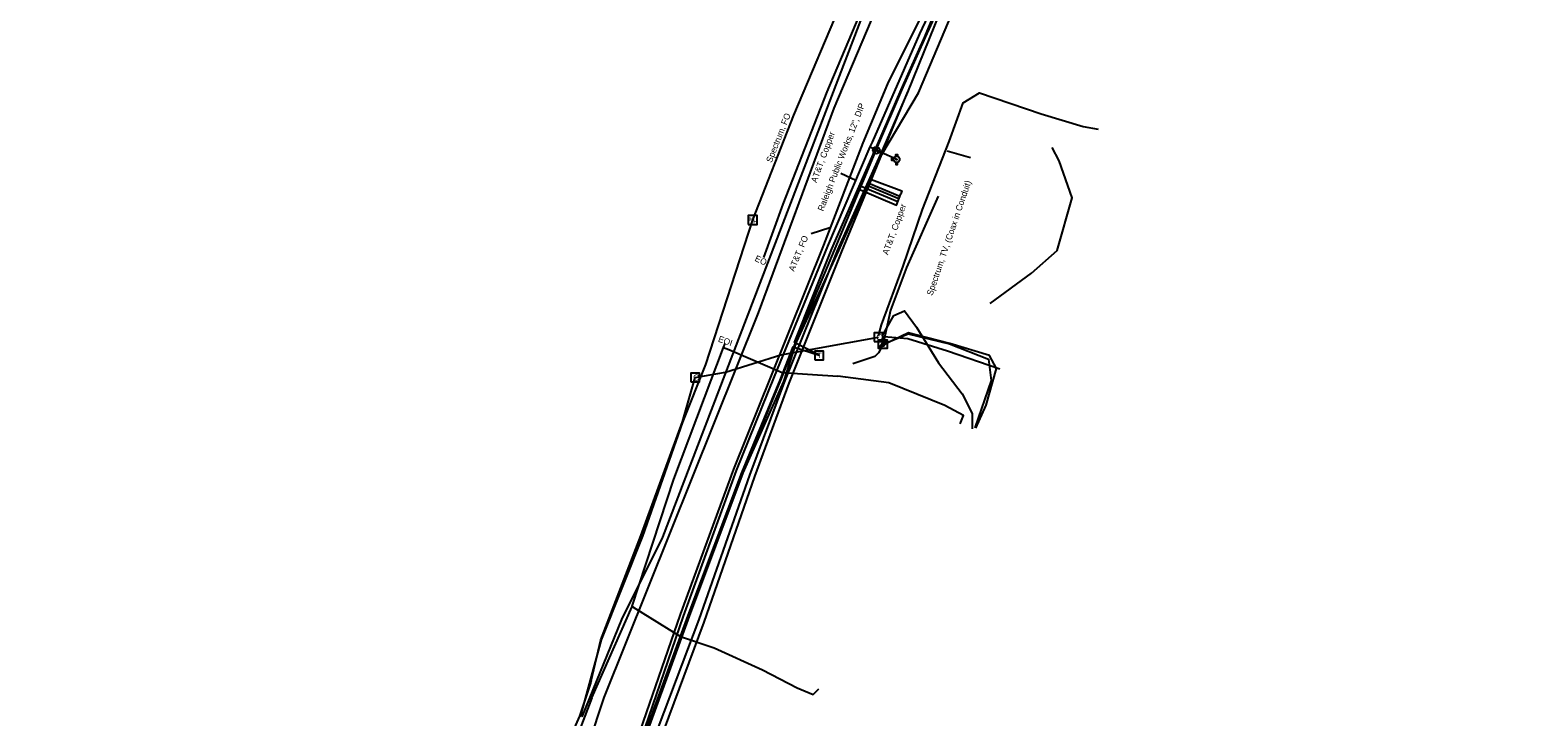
# Model space of a CAD drawing. Extents: x 2070721 to 2083340, y 729290 to 737883.
# Drawn here: x 2080953 to 2081917, y 733835 to 734274 of the extents above; entities that cross this region are included whole.
import ezdxf

# ---------------------------------------------------------------- set-up
doc = ezdxf.new("R2010")
doc.units = 0
for name, color, linetype in [('Exist Utilities Gas UG Line SUE LOS B', 7, 'Continuous'), ('Exist Utilities Gas Valve Text', 7, 'Continuous'), ('Exist Utilities Other Pole With Base Text', 7, 'Continuous'), ('Exist Utilities Other Unknown UG SUE LOS B', 7, 'Continuous'), ('Exist Utilities Power Transformer CELL', 7, 'Continuous'), ('Exist Utilities Power UG Cable SUE LOS B', 7, 'Continuous'), ('Exist Utilities Telephone Pedestal CELL', 7, 'Continuous'), ('Exist Utilities Telephone UG Cable SUE LOS C', 7, 'Continuous'), ('Exist Utilities Telephone UG Cable SUE LOS C Leader', 7, 'Continuous'), ('Exist Utilities Telephone UG Cable SUE LOS C Text', 7, 'Continuous'), ('Exist Utilities Telephone UG FO SUE LOS B', 7, 'Continuous'), ('Exist Utilities Telephone UG FO SUE LOS B Leader', 7, 'Continuous'), ('Exist Utilities Telephone UG FO SUE LOS B Text', 7, 'Continuous'), ('Exist Utilities TV Hand Hole CELL', 7, 'Continuous'), ('Exist Utilities TV Pedestal CELL', 7, 'Continuous'), ('Exist Utilities TV UG Cable SUE LOS B', 7, 'Continuous'), ('Exist Utilities TV UG Cable SUE LOS B Leader', 7, 'Continuous'), ('Exist Utilities TV UG Cable SUE LOS B Text', 7, 'Continuous'), ('Exist Utilities TV UG Cable SUE LOS C', 7, 'Continuous'), ('Exist Utilities TV UG FO Cable SUE LOS B', 7, 'Continuous'), ('Exist Utilities TV UG FO Cable SUE LOS B Text', 7, 'Continuous'), ('Exist Utilities Water Fire Hydrant CELL', 7, 'Continuous'), ('Exist Utilities Water UG Line SUE LOS B', 7, 'Continuous'), ('Exist Utilities Water UG Line SUE LOS B Leader', 7, 'Continuous'), ('Exist Utilities Water UG Line SUE LOS B Text', 7, 'Continuous'), ('Exist Utilities Water Valve CELL', 7, 'Continuous')]:
    doc.layers.add(name, color=color, linetype=linetype)

msp = doc.modelspace()

# ---------------------------------------------------------------- linework, layer by layer
at = {"layer": 'Exist Utilities Gas UG Line SUE LOS B'}
for points in [[(2081338.03, 733905.19), (2081338.21, 733905.54), (2081364.78, 733986.66), (2081384.36, 734038.69), (2081396.54, 734070.93), (2081397.51, 734073.37)], [(2081396.54, 734070.93), (2081399.83, 734069.53), (2081434.09, 734054.98), (2081469.65, 734052.56)], [(2081547.78, 734022.11), (2081549.89, 734027.5), (2081538.01, 734033.8), (2081502.22, 734048.37), (2081474.49, 734051.91), (2081469.65, 734052.56)], [(2081312.38, 733846.82), (2081338.03, 733905.19)], [(2081338.03, 733905.19), (2081340.5, 733903.66), (2081369.1, 733885.95), (2081390.43, 733878.76), (2081421.33, 733864.71), (2081443.53, 733853.28), (2081453.74, 733849.03), (2081457.45, 733852.48)], [(2081157.6, 733423.49), (2081157.75, 733423.93), (2081190.43, 733509.93), (2081219.7, 733588.19), (2081252.91, 733674.58), (2081286.02, 733770.88), (2081302.57, 733820.59), (2081312.47, 733846.89)]]:
    msp.add_lwpolyline(points, dxfattribs=at)
at = {"layer": 'Exist Utilities Other Unknown UG SUE LOS B'}
for points in [[(2081306.2, 733834.68), (2081331.52, 733896.97), (2081357.74, 733949.48), (2081551.49, 734455.55)], [(2081422.3, 734128.51), (2081434.71, 734162.6), (2081462.76, 734234.36), (2081499.05, 734320.38), (2081503.56, 734331.04)]]:
    msp.add_lwpolyline(points, dxfattribs=at)
at = {"layer": 'Exist Utilities Power Transformer CELL'}
msp.add_line((2081498.49, 734073.2), (2081498.49, 734073.2), dxfattribs=at)
msp.add_lwpolyline([(2081495.64, 734075.81), (2081501.2, 734075.81), (2081501.2, 734070.26), (2081495.64, 734070.26)], close=True, dxfattribs=at)
for points in [[(2081495.64, 734070.26), (2081498.29, 734074.2), (2081498.92, 734071.99), (2081501.2, 734075.81)], [(2081495.71, 734070.26), (2081498.29, 734073.99), (2081498.87, 734071.81), (2081501.2, 734075.66)]]:
    msp.add_lwpolyline(points, dxfattribs=at)
at = {"layer": 'Exist Utilities Power UG Cable SUE LOS B'}
for points in [[(2081566.99, 734098.99), (2081593.32, 734118.39), (2081609.81, 734133.03), (2081619.44, 734166.59), (2081611.13, 734190.33), (2081606.68, 734198.77)], [(2081533.76, 734167.78), (2081513.41, 734122.01), (2081503.32, 734094.68), (2081498.5, 734073.2)], [(2081498.49, 734073.2), (2081495.51, 734067.56), (2081493.34, 734065.2), (2081479.14, 734060.39)], [(2081557.74, 734019.38), (2081564.5, 734034.09), (2081571.11, 734057.42), (2081566.57, 734065.71), (2081541.21, 734073.53), (2081514.71, 734080.22), (2081499.18, 734072.89)], [(2081499.39, 734072.79), (2081502.13, 734074.42), (2081514.62, 734079.56), (2081541, 734073.24), (2081566.01, 734063.53), (2081567.68, 734049.7), (2081557.19, 734019.59)]]:
    msp.add_lwpolyline(points, dxfattribs=at)
at = {"layer": 'Exist Utilities Telephone Pedestal CELL'}
msp.add_line((2081457.55, 734065.88), (2081457.55, 734065.88), dxfattribs=at)
msp.add_lwpolyline([(2081454.82, 734063.06), (2081460.42, 734063.06), (2081460.42, 734068.65), (2081454.82, 734068.65), (2081454.82, 734063.06)], dxfattribs=at)
at = {"layer": 'Exist Utilities Telephone UG Cable SUE LOS C'}
for points in [[(2080953.21, 732796.69), (2081054.09, 733077.62), (2081111.09, 733245.57), (2081176.08, 733423.78), (2081231.97, 733580.28), (2081320.16, 733847.08), (2081418.84, 734093.09), (2081467.34, 734224.03), (2081494.06, 734287.2), (2081526.74, 734352.01), (2081556, 734404.62), (2081808.13, 734757.73), (2081845.73, 734804.26), (2081874.67, 734821.58), (2081898.66, 734810.94), (2081917.15, 734795.51)], [(2081296.4, 733658.15), (2081287.8, 733664.8), (2081303.6, 733706.37), (2081324.3, 733763.14), (2081337.34, 733798.98), (2081373.91, 733899.45), (2081408.19, 733990.78), (2081432.67, 734050.1), (2081441.11, 734071.31), (2081457.65, 734065.9), (2081441.97, 734074.17), (2081465.76, 734134.1), (2081494.56, 734199.64), (2081510.1, 734235.63), (2081525.23, 734269.67), (2081532.48, 734287.03), (2081544.5, 734311.63), (2081547.42, 734317.11)], [(2081296.31, 733658.4), (2081289.16, 733664.06), (2081304.03, 733706.05), (2081324.8, 733762.93), (2081337.87, 733799.07), (2081374.5, 733899.39), (2081408.89, 733991.2), (2081433.1, 734049.99), (2081442.72, 734074.23), (2081467.51, 734133.17), (2081494.99, 734199.31), (2081510.48, 734235.4), (2081525.69, 734269.34), (2081544.76, 734311.53), (2081547.99, 734317.07)], [(2081296.39, 733658.2), (2081307.45, 733685.25), (2081318.77, 733704.29), (2081345.73, 733792.08), (2081384.21, 733895.19), (2081416.52, 733988.47), (2081438.43, 734048.05), (2081472.15, 734132.3), (2081497.77, 734194.3), (2081521.27, 734233.79), (2081552.24, 734307.58), (2081554.35, 734311.73)], [(2081296.32, 733658.45), (2081292.23, 733667.87), (2081304.13, 733678.02), (2081310.51, 733703.91), (2081344.1, 733799.36), (2081380.98, 733896.99), (2081413.3, 733989.25), (2081435.43, 734048.8), (2081469.68, 734133.31), (2081498.8, 734198.46), (2081514.35, 734234.28), (2081535.34, 734285.71)], [(2081296.61, 733659.46), (2081294.36, 733663.37), (2081305.04, 733689.21), (2081304.27, 733706.32), (2081325.1, 733762.82), (2081338.41, 733798.86), (2081374.68, 733899.14), (2081409.12, 733990.75), (2081435.11, 734049.06), (2081443.22, 734074.28), (2081470.18, 734132.86), (2081499.3, 734198.06), (2081514.4, 734234.31)]]:
    msp.add_lwpolyline(points, dxfattribs=at)
at = {"layer": 'Exist Utilities Telephone UG Cable SUE LOS C Leader'}
for p, q in [((2081484.48, 734174.03), (2081507.94, 734164.17)), ((2081488.23, 734174.81), (2081508.68, 734166.13)), ((2081489.45, 734176.03), (2081509.23, 734167.66))]:
    msp.add_line(p, q, dxfattribs=at)
for points in [[(2081491.14, 734178.26), (2081510.46, 734171.14), (2081509.82, 734169.24)], [(2081482.62, 734172.39), (2081507.12, 734161.92), (2081509.82, 734169.24)]]:
    msp.add_lwpolyline(points, dxfattribs=at)
at = {"layer": 'Exist Utilities Telephone UG FO SUE LOS B'}
msp.add_lwpolyline([(2081248.81, 733567.64), (2081281.2, 733657.22), (2081333.49, 733797.21), (2081369.06, 733900.16), (2081403.11, 733993), (2081427.18, 734053.08), (2081460.75, 734136.42), (2081485.85, 734201.8), (2081501.51, 734239.63), (2081538.45, 734313.8), (2081542.88, 734322.62)], dxfattribs=at)
at = {"layer": 'Exist Utilities Telephone UG FO SUE LOS B Leader'}
msp.add_line((2081464.59, 734147.47), (2081452.54, 734143.52), dxfattribs=at)
at = {"layer": 'Exist Utilities TV Hand Hole CELL'}
msp.add_line((2081415.06, 734152.42), (2081415.06, 734152.42), dxfattribs=at)
msp.add_lwpolyline([(2081412.19, 734149.55), (2081417.94, 734149.55), (2081417.94, 734155.3), (2081412.19, 734155.3), (2081412.19, 734149.55)], dxfattribs=at)
at = {"layer": 'Exist Utilities TV Pedestal CELL'}
for p, q in [((2081495.55, 734077.52), (2081495.55, 734077.52)), ((2081378.38, 734051.63), (2081378.38, 734051.63))]:
    msp.add_line(p, q, dxfattribs=at)
for points in [[(2081492.78, 734074.75), (2081498.33, 734074.75), (2081498.33, 734080.3), (2081492.78, 734080.3), (2081492.78, 734074.75)], [(2081375.61, 734048.85), (2081381.16, 734048.85), (2081381.16, 734054.4), (2081375.61, 734054.4), (2081375.61, 734048.85)]]:
    msp.add_lwpolyline(points, dxfattribs=at)
at = {"layer": 'Exist Utilities TV UG Cable SUE LOS B'}
for points in [[(2081495.68, 734078.41), (2081497.44, 734085.32), (2081511.29, 734122.81), (2081523.68, 734159.18), (2081540.68, 734202.67), (2081549.71, 734227.45), (2081560.24, 734233.78), (2081599.68, 734220.27), (2081626.49, 734212.19), (2081636.02, 734210.48)], [(2081498.25, 734078.67), (2081505.35, 734091.29), (2081512.22, 734094.34), (2081519.8, 734083.82), (2081533.95, 734061.11), (2081549.19, 734041.27), (2081555.57, 734028.72), (2081555.57, 734018.83)], [(2081378.38, 734051.63), (2081388.01, 734053.44), (2081397.72, 734055.21), (2081433.17, 734066.11), (2081495.5, 734077.4)], [(2081573.07, 734056.98), (2081539.64, 734068.54), (2081514.32, 734076.46), (2081498.99, 734077.79)]]:
    msp.add_lwpolyline(points, dxfattribs=at)
at = {"layer": 'Exist Utilities TV UG Cable SUE LOS B Leader'}
msp.add_line((2081539.58, 734196.78), (2081554.51, 734192.46), dxfattribs=at)
at = {"layer": 'Exist Utilities TV UG Cable SUE LOS C'}
for points in [[(2081311.88, 733857.73), (2081318.02, 733883.97), (2081343.7, 733950.47), (2081370.25, 734023.44), (2081378.31, 734051.68)], [(2081311.88, 733857.73), (2081311.69, 733856.75), (2081304.36, 733835.18), (2081292.68, 733808.59), (2081285.24, 733806.52)]]:
    msp.add_lwpolyline(points, dxfattribs=at)
at = {"layer": 'Exist Utilities TV UG FO Cable SUE LOS B'}
msp.add_lwpolyline([(2081305.07, 733834.62), (2081318.51, 733883.96), (2081344.94, 733950.24), (2081370.6, 734023.22), (2081385.26, 734060), (2081415.18, 734152.65), (2081441.55, 734219.41), (2081473.57, 734295.5), (2081490.54, 734320.82), (2081495.24, 734327.83)], dxfattribs=at)
at = {"layer": 'Exist Utilities Water Fire Hydrant CELL'}
msp.add_line((2081507.14, 734191.19), (2081507.14, 734191.19), dxfattribs=at)
for points in [[(2081505.23, 734191.7), (2081503.94, 734191.7), (2081503.94, 734190.67), (2081505.23, 734190.67)], [(2081506.62, 734193.1), (2081506.62, 734194.39), (2081507.65, 734194.39), (2081507.65, 734193.07)], [(2081506.62, 734189.27), (2081506.62, 734187.99), (2081507.65, 734187.99), (2081507.65, 734189.3)]]:
    msp.add_lwpolyline(points, dxfattribs=at)
for radius in [1.98, 0.243]:
    msp.add_circle((2081507.14, 734191.19), radius, dxfattribs=at)
at = {"layer": 'Exist Utilities Water UG Line SUE LOS B'}
for points in [[(2081490.29, 734199.14), (2081491.68, 734202.17), (2081522.1, 734271.61), (2081541.68, 734313.21), (2081545.19, 734320.14)], [(2081335.25, 733795.02), (2081336.53, 733799.05), (2081370.86, 733898.95), (2081404.78, 733992.12), (2081429.05, 734052.38), (2081463.19, 734135.61), (2081490.29, 734199.14)], [(2081490.29, 734199.14), (2081496.9, 734195.96), (2081507.42, 734191.29)]]:
    msp.add_lwpolyline(points, dxfattribs=at)
at = {"layer": 'Exist Utilities Water UG Line SUE LOS B Leader'}
msp.add_line((2081481.14, 734177.71), (2081471.52, 734182.16), dxfattribs=at)
at = {"layer": 'Exist Utilities Water Valve CELL'}
msp.add_lwpolyline([(2081495.74, 734198.64), (2081492.59, 734195.49), (2081494.16, 734197.07), (2081495.74, 734195.49), (2081492.59, 734198.64)], dxfattribs=at)
msp.add_circle((2081494.16, 734197.07), 2.23, dxfattribs=at)

# ---------------------------------------------------------------- texts
at = {"layer": 'Exist Utilities Gas Valve Text'}
msp.add_text('EOI', height=4, rotation=340.64453, dxfattribs=at).set_placement((2081392.69, 734074.74))
at = {"layer": 'Exist Utilities Other Pole With Base Text'}
msp.add_text('EOI', height=4, rotation=335.04332, dxfattribs=at).set_placement((2081416.08, 734126.45))
at = {"layer": 'Exist Utilities Telephone Pedestal CELL'}
msp.add_text('T', height=3.42, dxfattribs=at).set_placement((2081456.42, 734064.17))
at = {"layer": 'Exist Utilities Telephone UG Cable SUE LOS C Text'}
for rotation, p in [(69.67412, (2081455.95, 734176)), (69.83652, (2081501.65, 734129.74))]:
    msp.add_text('AT&T, Copper', height=4, rotation=rotation, dxfattribs=at).set_placement(p)
at = {"layer": 'Exist Utilities Telephone UG FO SUE LOS B Text'}
msp.add_text('AT&T, FO', height=4, rotation=67.51048, dxfattribs=at).set_placement((2081441.61, 734119.19))
at = {"layer": 'Exist Utilities TV Hand Hole CELL'}
for p in [(2081412.98, 734151.77), (2081415.55, 734150.31)]:
    msp.add_text('H', height=2.5, dxfattribs=at).set_placement(p)
at = {"layer": 'Exist Utilities TV Pedestal CELL'}
for p in [(2081494.24, 734075.52), (2081377.08, 734049.63)]:
    msp.add_text('C', height=4, dxfattribs=at).set_placement(p)
at = {"layer": 'Exist Utilities TV UG Cable SUE LOS B Text'}
msp.add_text('Spectrum, TV, (Coax in Conduit)', height=4, rotation=71.19058, dxfattribs=at).set_placement((2081530.06, 734103.77))
at = {"layer": 'Exist Utilities TV UG FO Cable SUE LOS B Text'}
msp.add_text('Spectrum, FO ', height=4, rotation=68.44131, dxfattribs=at).set_placement((2081427.32, 734188.83))
at = {"layer": 'Exist Utilities Water UG Line SUE LOS B Text'}
msp.add_text('Raleigh Public Works, 12", DIP ', height=4, rotation=68.59227, dxfattribs=at).set_placement((2081460.26, 734157.73))

doc.saveas('drawing.dxf')
